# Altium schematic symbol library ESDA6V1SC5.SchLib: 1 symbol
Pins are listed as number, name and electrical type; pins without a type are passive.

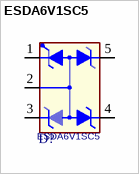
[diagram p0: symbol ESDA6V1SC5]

## ESDA6V1SC5
designator D?
footprint ST_SOT23-5L
pins: 1, 2, 3, 4, 5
